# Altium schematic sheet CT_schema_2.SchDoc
size 258 x 142 mm
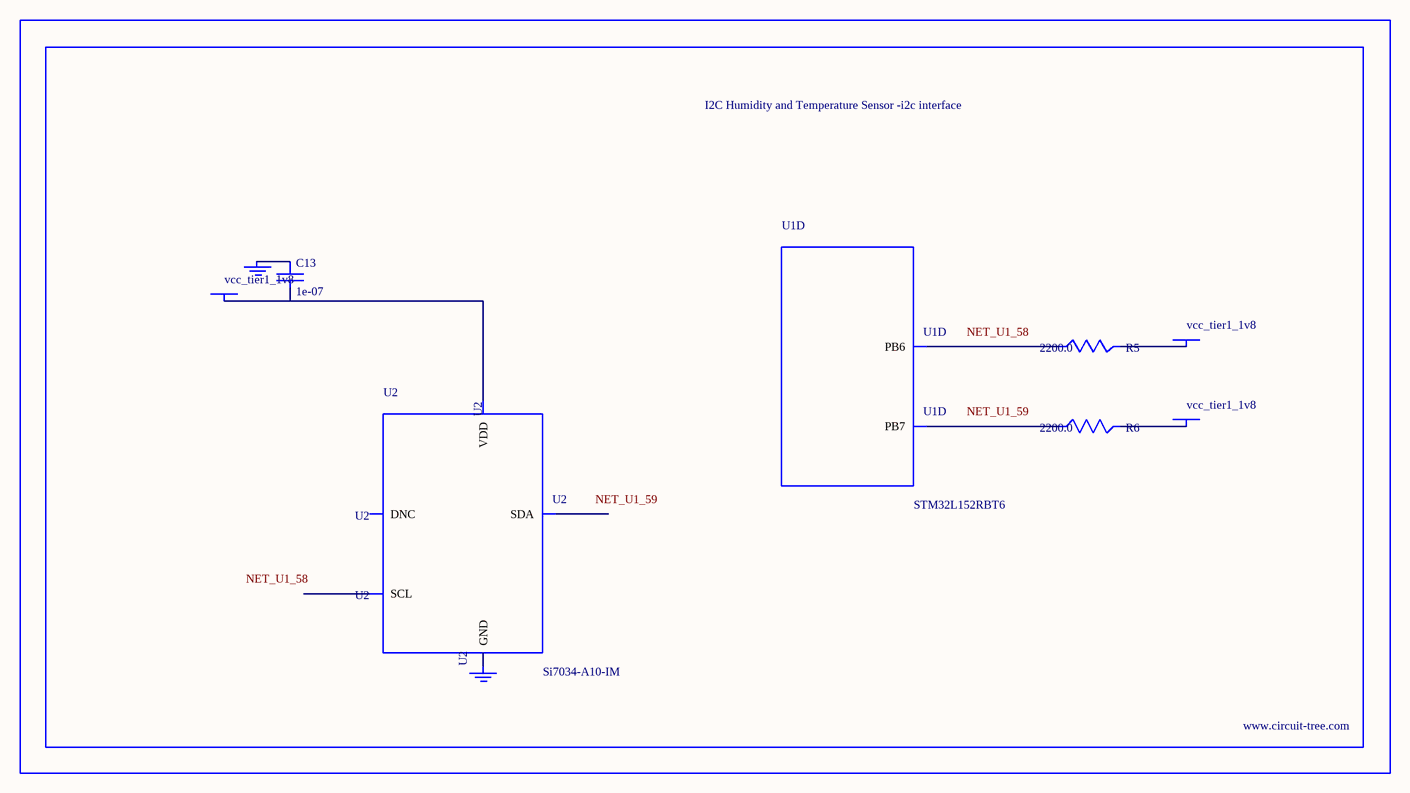
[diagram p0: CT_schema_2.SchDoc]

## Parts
BORDER1  (no value)
C13  1e-07  [C0402]
GND_INSTANCE_1_0  (no value)
GND_INSTANCE_1_1  (no value)
POWER_INSTANCE_1_0  vcc_tier1_1v8
POWER_INSTANCE_1_1  vcc_tier1_1v8
POWER_INSTANCE_1_2  vcc_tier1_1v8
R5  2200.0  [R0603]
R6  2200.0  [R0603]
U1  STM32L152RBT6  [LQFP64]  (part D of 6)
U2  Si7034-A10-IM  [SI7034-A10-IM]

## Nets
NetC13_1: C13.1 GND_INSTANCE_1_0.0(GND)
NetC13_2: C13.2 POWER_INSTANCE_1_0.0(PWR) U2.1(VDD)
NetGND_INSTANCE_1_1_0: GND_INSTANCE_1_1.0(GND) U2.5(GND)
NetPOWER_INSTANCE_1_1_0: POWER_INSTANCE_1_1.0(PWR) R5.2
NetPOWER_INSTANCE_1_2_0: POWER_INSTANCE_1_2.0(PWR) R6.2
NetR5_1: R5.1 U1.58(PB6)
NetR6_1: R6.1 U1.59(PB7)

Not connected (* = marked no-connect by the designer): U2 2(SCL) 3(DNC) 4(SDA)

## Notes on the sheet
- Labels drawn without touching a wire or pin: NET_U1_58, NET_U1_59

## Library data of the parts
BORDER1 = BORDER_PAGE1
C13 = C0402C104K3RACTU
GND_INSTANCE_1_0 GND_INSTANCE_1_1 = GND
POWER_INSTANCE_1_0-POWER_INSTANCE_1_2 = PWR
R5 R6 = RC0603JR-072K2L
